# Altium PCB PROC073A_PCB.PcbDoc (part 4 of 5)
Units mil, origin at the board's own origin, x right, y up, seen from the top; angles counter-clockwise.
Board outline 2165.35 x 2165.35 mil, 6 copper layers (Top Layer, L2, L3, L4, L5, Bottom Layer), stack 55.77 mil thick; 284 components, 233 nets, 945 pads, 1419 vias.
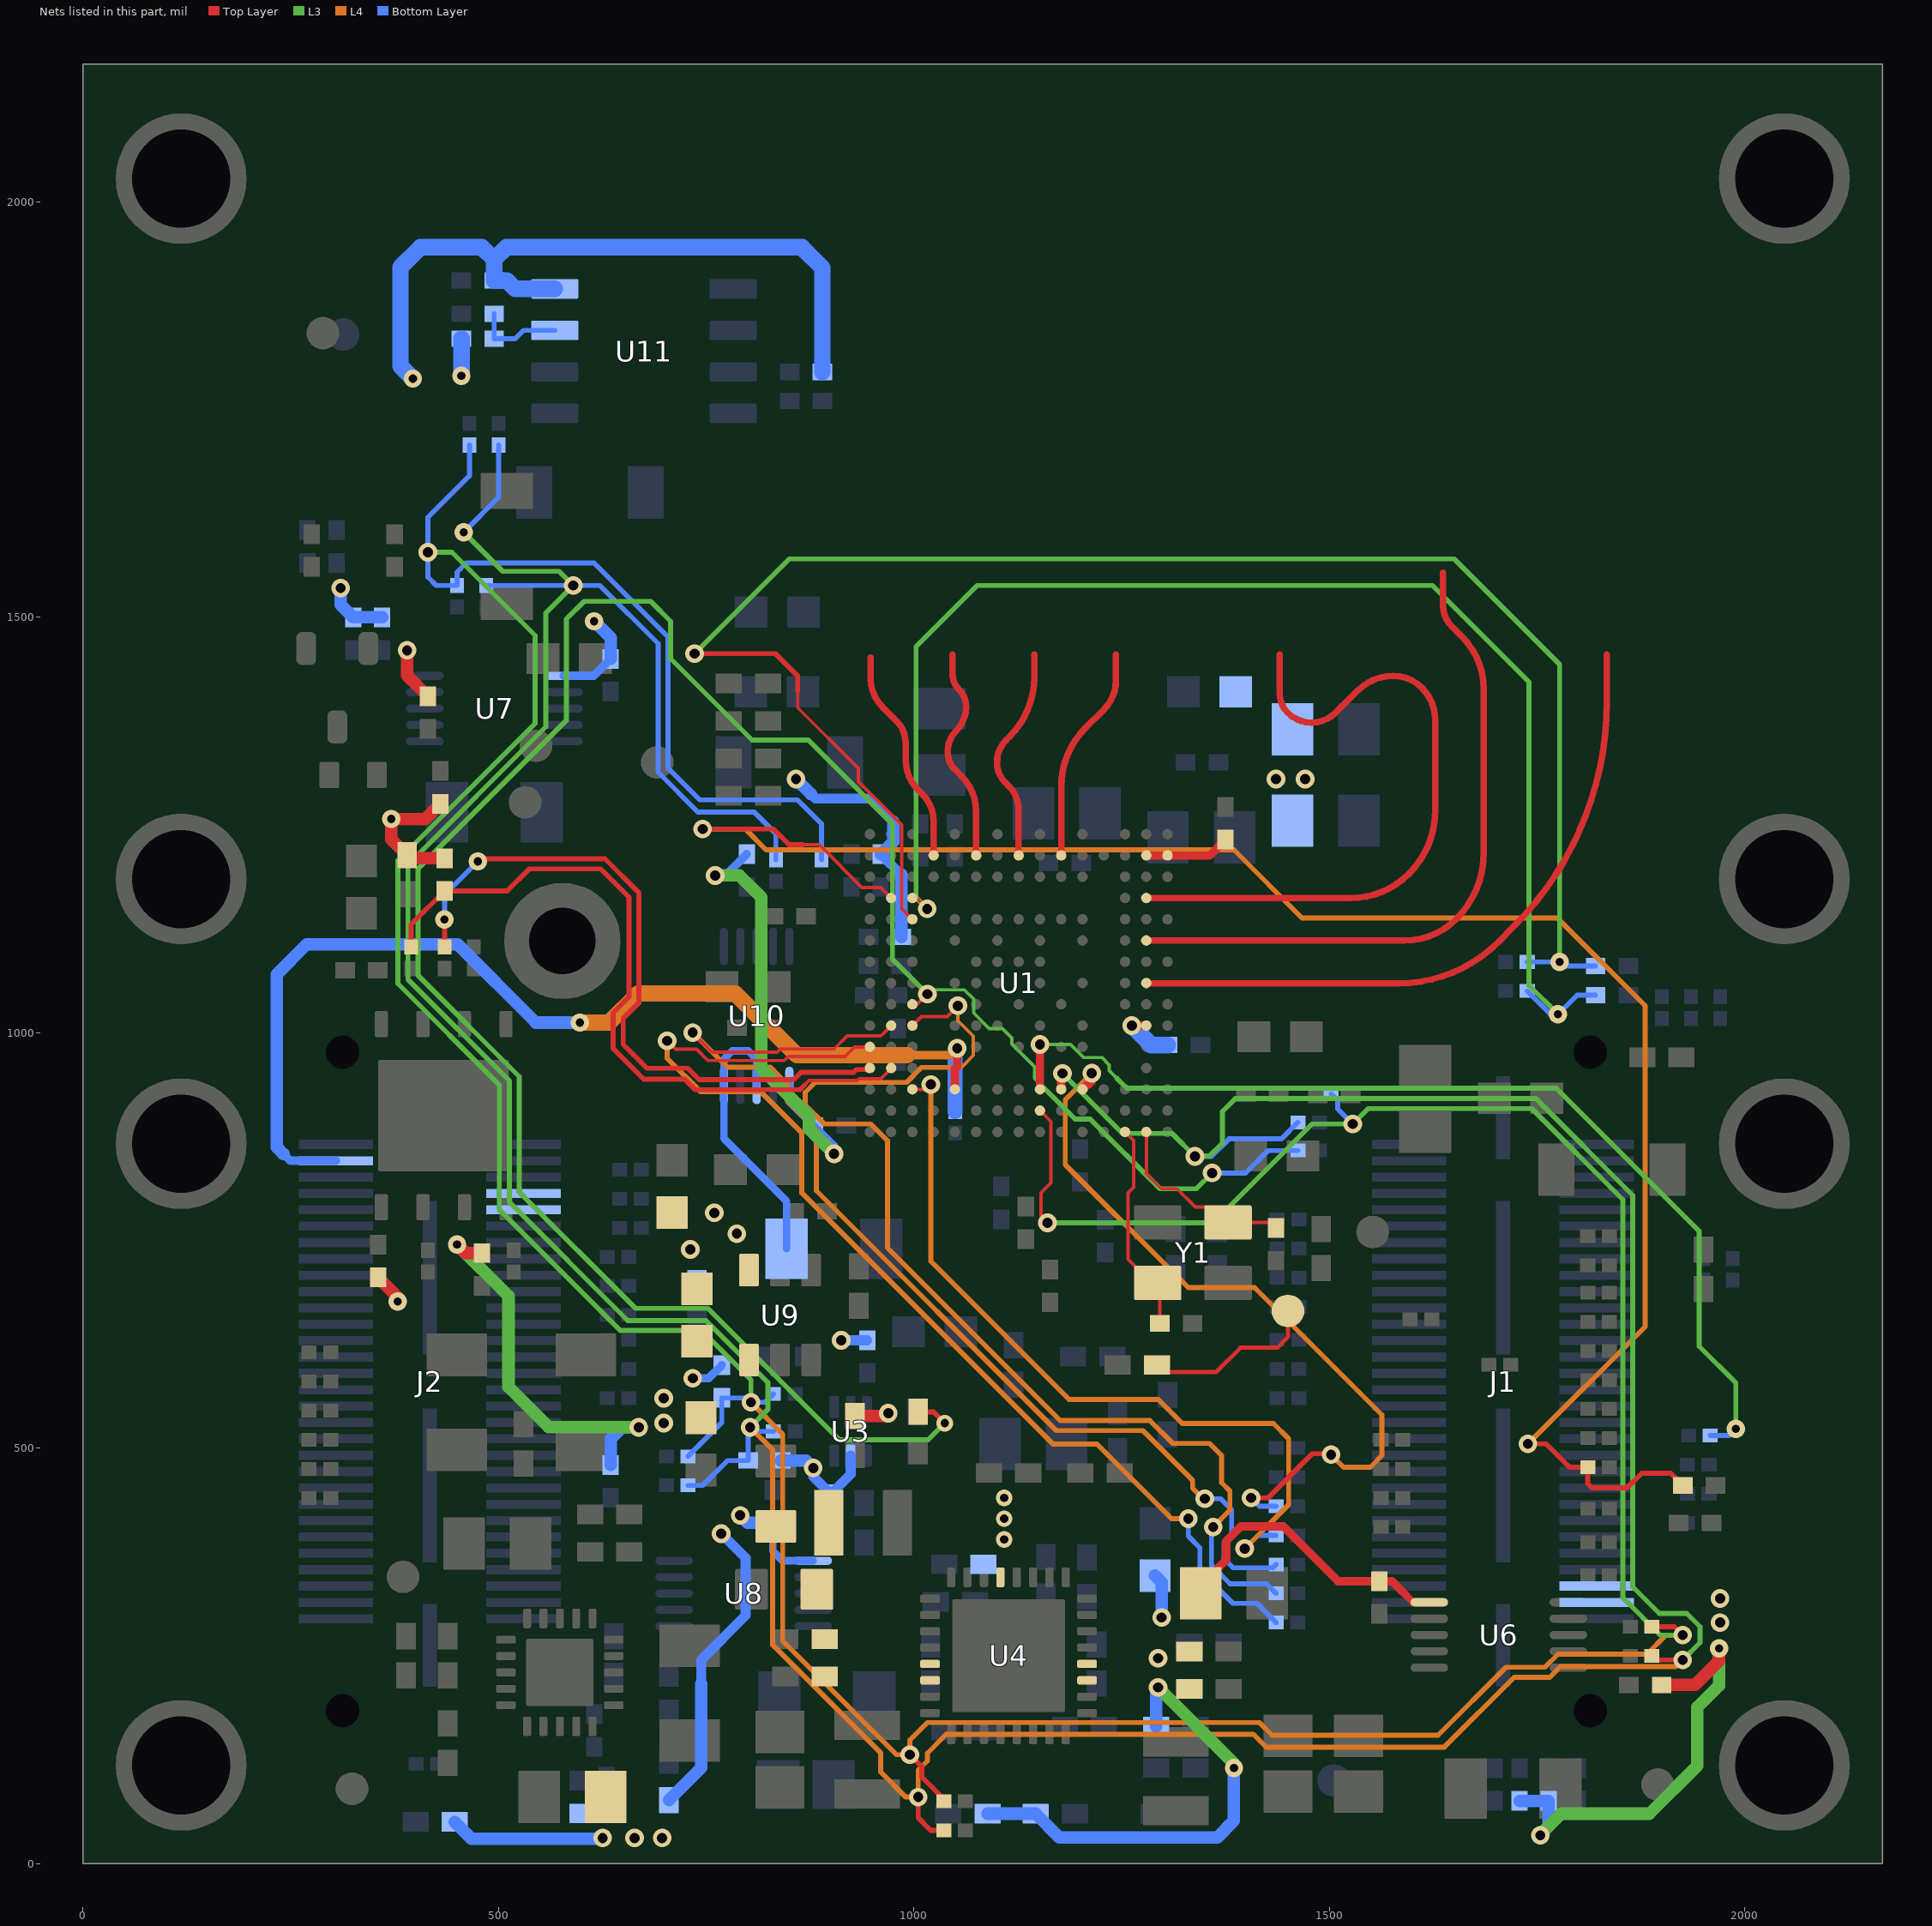
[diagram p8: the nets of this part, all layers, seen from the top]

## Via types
v1: diameter 13.77/15.74 (per signal layer), hole 5.9, Top Layer to L2, tented both sides, 894 vias
v2: diameter 22.4, hole 12.2, Top Layer to Bottom Layer, tented both sides, 340 vias
v3: diameter 13.78/15.75 (per signal layer), hole 5.9, Top Layer to L2, tented both sides, 72 vias
v4: diameter 22, hole 10, Top Layer to Bottom Layer, tented both sides, 54 vias
v5: diameter 20, hole 10, Top Layer to Bottom Layer, tented both sides, 35 vias
v6: diameter 13.77/15.74 (per signal layer), hole 5.9, Top Layer to L2, tented top, 14 vias
v7: diameter 19.68, hole 7.87, Top Layer to Bottom Layer, tented both sides, 9 vias
v8: diameter 13.78/15.75 (per signal layer), hole 5.9, Top Layer to L2, tented top, 1 vias

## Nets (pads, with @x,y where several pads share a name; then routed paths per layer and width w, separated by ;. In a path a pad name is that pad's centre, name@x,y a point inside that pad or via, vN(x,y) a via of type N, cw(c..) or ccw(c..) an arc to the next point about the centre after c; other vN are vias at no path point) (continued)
RADAR_QSPI_D3: R49.1 R51.2 U1.P12 | length 887.1
  Top Layer w4: 868.06,936.7 873.56,942.2 931.63,942.2 933.98,944.55 960.14,944.55 U1.P12@972.64,957.05
  Top Layer w6: R51.2@395,1102.99 395,1130.31 R49.1@435,1170.32 510.31,1170.31 537.01,1197.01 623.01,1197.01 657,1163.03 657,1043 638,1024 638,980.74 674.74,944 723.68,944 736.48,931.2 862.56,931.2 868.06,936.7
RADAR_QSPI_SCLK: R48.2 U1.R12 | length 842.2
  Top Layer w4: U1.R12@945.56,955.56 U1.R12@947.05,957.05
  Top Layer w6: R48.2@435,1102.99 v4(435,1135.99) ; v4(475,1206) 478.01,1209.01 627.98,1209.01 669,1168 669,1036 650,1017 650,985.71 678.71,957 727.65,957 741.31,943.34 855.27,943.34 864.13,952.2 927.49,952.2 930.85,955.56 U1.R12@945.56,955.56
  Bottom Layer w6: v4(435,1135.99) 435,1166 v4(475,1206)
RADAR_RS232RX: R38.1 R154.1 U1.N4 | length 1678.4
  Top Layer w4: U1.N4@998.03,1161.98 1002.76,1161.98 v2(1015.87,1148.87)
  L3 w5.98: v2(1015.87,1148.87) 1002.43,1162.31 1002.43,1464.43 1076,1538 1624,1538 1740,1422 1740,1057 v4(1775,1022)
  Bottom Layer w5.98: R38.1@1737.99,1050 1765.99,1022 v4(1775,1022) 1798,1045 R154.1@1820.32,1045
RADAR_RS232TX: R40.1 R153.1 U1.N5 | length 2068.6
  Top Layer w4: 860,1410.95 860,1391 933,1318 933,1301.91 985.23,1249.68 985.23,1246.17 ; 985.28,1246.17 985.28,1149.13 U1.N5@998.23,1136.18
  Top Layer w6: v2(736,1456) 833.25,1456 860,1429.25 860,1410.95
  L3 w6: v2(736,1456) 850,1570 1650,1570 1777,1443 v4(1777,1085)
  Bottom Layer w6: R40.1@1737.99,1085 v4(1777,1085) 1782,1080 R153.1@1820.32,1080
RADAR_SCL: R25.2 R37.1 R53.1 R56.1 R89.1 R108.2 R109.2 R143.2 R159.2 U1.G14 | length 5694.7
  Top Layer w4: U1.G14@1151.57,906.07 1164.57,893.07 1164.57,819.01 1152.89,807.33 1152.89,778.7 v2(1160.59,771)
  Top Layer w6: v2(995,131) 1009.5,116.5 1009.5,104.07 1035.75,77.81 R89.1@1035.75,75 ; R25.2@1887.99,285 1915,285 v2(1925,275)
  L3 w6: v2(415,1578) 444,1578 544,1478 544,1371.91 379,1206.91 379,1059 501,937 501,787 646.5,641.5 744.5,641.5 803.74,582.26 v2(803.74,555) ; v2(1160.59,771) 1360,771 1479,890 v2(1528,890) 1546.52,908.52 1743.48,908.52 1853,799 1853,320 1898,275 v2(1925,275)
  L4 w6: v2(803.74,555) 842,516.74 842,268 979,131 v2(995,131) 995,148.42 1016.23,169.65 1415.8,169.65 1430.91,154.53 1630.76,154.53 1712.36,236.14 1759.14,236.14 1775,252 1882,252 1905,275 v2(1925,275)
  Bottom Layer w6: R159.2@465,1707.01 465,1670 415,1620 v2(415,1578) 415,1548 425.01,1537.99 R108.2@450,1537.99 450,1553.99 461,1565 615,1565 704,1476 704,1318.2 742.08,1280.12 859.88,1280.12 888.74,1251.26 R143.2@888.74,1207.99 ; R109.2@727.99,490 768.74,530.75 R53.1@768.74,560.32 798.43,560.31 v2(803.74,555) 820.75,555 R56.1@830.75,565 ; R37.1@1502.01,926 1509.94,918.07 1509.94,908.06 v2(1528,890) v2@1526.45,890
RADAR_SDA: R29.2 R34.1 R52.1 R55.1 R88.1 R110.2 R111.2 R144.2 R160.2 U1.F13 | length 5642.3
  Top Layer w6: v2(1005,80) 1005,55 1020,40 R88.1@1035.75,40 ; R29.2@1887.99,250 1892.99,245 v2(1925,245)
  Top Layer w10: U1.F13@1177.16,931.66 1177.15,949.42 v2(1178.55,950.82)
  L3 w6: v4(458,1602) 505,1555 572.99,1555 v2(590,1537.99) 557,1504.99 557,1367.94 391,1201.94 391,1063.97 513,941.97 513,796 655.5,653.5 749.53,653.5 824.01,579.01 824.01,546.27 v2(802.74,525) ; v2(1178.55,950.82) 1250.82,878.55 1310.44,878.55 v2(1338,851) 1338.2,851.2 1355.2,851.2 1371,867 1371,904.83 1386.69,920.52 1748.45,920.52 1865,803.97 1865,333 1897,301 1930,301 1946,285 1946,266 v2(1925,245)
  L4 w6: v2(802.74,525) 830,497.74 830,263.03 960,133.03 960,110 990,80 v2(1005,80) 1005,112.43 1016,123.43 1016,132.87 1038.6,155.47 1408.41,155.47 1423.76,140.11 1638.15,140.11 1722.17,224.14 1765.14,224.14 1778.03,237.03 1917.03,237.03 v2(1925,245)
  Bottom Layer w6: v4(458,1602) 500,1644 R160.2@500,1707.01 ; R110.2@485,1537.99 v2(590,1537.99) 622.01,1537.99 692,1468 692,1313.23 740.03,1265.2 807.8,1265.2 833.74,1239.26 R144.2@833.74,1207.99 ; R111.2@727.99,455 745.55,455 775.55,485 R52.1@800.32,485 800.31,522.57 v2(802.74,525) 807.74,520 R55.1@830.75,520 ; v2(1338,851) 1358,851 1379,872 1442.01,872 R34.1@1462.01,892
RADAR_SPICLK1: R9.1 U1.E13 | length 928.1
  Top Layer w6: v2(1405.74,440) 1426,440 1479.2,493.2 v2@1501,493.2
  Top Layer w10: U1.E13@1202.75,931.66 1208.65,937.57 1210.37,937.57 1213.87,941.08 v2(1213.87,951.07)
  L4 w6: v2(1213.87,951.07) 1182,919.19 1182,841 1330,693 1409.75,693 1563,539.75 1563,491 1549,477 1517,477 v2(1502,492) ; v2@1502.11,493.2 v2@1502.65,492.65
  Bottom Layer w6: v2(1405.74,440) 1415.74,430 R9.1@1435.75,430
RADAR_SYNC_IN: R36.2 R155.2 U1.P4 | length 2302.7
  Top Layer w4: 865.59,1226 885.9,1226 937.33,1174.57 959.84,1174.57 U1.P4@972.43,1161.98
  Top Layer w6: v2(745.59,1245) 830.59,1245 849.59,1226 865.59,1226 ; v2(1738.74,505) 1760.75,505 1788.9,476.85 R36.2@1810.75,476.85 1810.75,457.25 1816,452 1858,452 1875.8,469.8 1910.51,469.8 R155.2@1925.31,455
  L4 w6: v2(745.59,1245) 796.96,1245 821.96,1220 1384.92,1220 1467.17,1137.75 1774.25,1137.75 1879.76,1032.24 1879.76,646.02 v2(1738.74,505)
RADAR_SYNC_OUT_SOP1: R16.2 U1.G13 | length 1235.2
  Top Layer w10: v2(1151.47,985.62) 1151.47,967.42 1151.56,967.33 U1.G13@1151.57,931.66
  L3 w4: v2(1151.47,985.62) 1188.38,985.62 1204,970 1226,970 1235,961 1235,954 1244.04,944.96
  L3 w6: 1244.04,944.96 1256,933 1772.92,933 1945,760.92 1945,622.52 1989,578.52 v4(1989,523)
  Bottom Layer w6: R16.2@1957.99,515 1981,515 v4(1989,523)
RADAR_TCK: R6.2 U1.P10 | length 1340.2
  Top Layer w4: v2(733.59,1000) 757.25,976.34 835.53,976.34 839.39,980.2 903.92,980.2 919.59,995.87 959.83,995.87 962.72,998.76 962.82,998.76 U1.P10@972.43,1008.43 U1.P10@972.43,1008.43
  L4 w5.98: v2(733.59,1000) 775.11,958.48 826.52,958.48 847.57,937.43 847.57,917.44 882.35,882.66 882.35,809.72 1171.05,521.01 1275.43,521.01 1335.19,461.25 1335.19,451.53 1347.73,439 v2(1350,439)
  Bottom Layer w5.98: v2(1350,439) 1369,439 1382.29,425.7 1382.29,396.01 1373.02,386.74 1373.02,366.98 1384,356 1431.75,356 R6.2@1435.75,360
RADAR_TDI: R5.1 U1.R11 | length 1366.2
  Top Layer w4: v2(703,990) 713,980 738.37,980 752.03,966.34 843.97,966.34 848.83,971.2 916.79,971.2 928.23,982.64 U1.R11@947.05,982.64
  L4 w6: v2(703,990) 703,969 743.4,928.59 815.62,928.59 865.09,879.12 865.09,806.91 1167.08,504.92 1220,504.92 1309.91,415 v2(1330,415)
  Bottom Layer w6: v2(1330,415) 1330,394 1344,380 1344,352.67 1383.67,313 1412.75,313 R5.1@1435.75,290
RADAR_TDO_SOP0: R4.2 U1.N13 | length 955
  Top Layer w4: U1.N13@998.03,931.66 1014.37,931.67 v2(1020.27,937.57)
  L4 w5.98: v2(1020.27,937.57) 1020.27,724.72 1186.6,558.4 1293.91,558.4 1322.79,529.52 1432.48,529.52 1450.82,511.18 1450.82,431.82 v2(1398,379)
  Bottom Layer w5.98: v2(1398,379) 1414,395 R4.2@1435.75,395
RADAR_TMS: R8.2 U1.N10 | length 1356.4
  Top Layer w4: U1.N10@998.03,1008.43 1008.97,1019.39 1039.8,1019.39 v2(1052.67,1032.26)
  L4 w4.02: 1048,958 1056.74,958 1071.23,972.49 1071.23,995.77 1052.67,1014.32 v2(1052.67,1032.26)
  L4 w6: 1048,958 1009,958 991,940 881,940 869,928 869,912.97 891.97,890 948,890 968,870 968,741.03 1176.02,533.01 1283.99,533.01 1311.47,505.53 1355.69,505.53 1370.2,491.01 1370.2,458.37 1380.2,448.37 1380.2,425.2 v2(1360,405)
  Bottom Layer w6: v2(1360,405) 1358.01,403.01 1358.01,358.99 1380.5,336.5 1424.25,336.5 R8.2@1435.75,325
RADAR_VBGAP: C6.2 U1.B10 | length 70.4
  Top Layer w10: v2(1262.07,1008.44) U1.B10@1279.52,1008.43
  Bottom Layer w20: v2(1262.07,1008.44) 1285.51,985 C6.2@1305.31,985
RADAR_VOUT_PA: C4.2 C7.2 C8.2 R1.2 U1.A2 U1.B2 | length 102.2
  Top Layer w10: U1.B2@1279.72,1212.95 1355.41,1212.95 C4.2@1374.18,1231.72
  other v2: 1435.59,1305 1470.59,1305
RADAR_VSENSE: R77.1 TP7.1 | length 210.1
  Top Layer w5: R77.1@1292.36,600 1300.89,591.48 1363.55,591.48 1392.82,620.75 1437.23,620.75 1450,633.52 TP7.1@1450,665
RADAR_WARMRST: R64.2 R98.1 U1.N9 | length 2868.1
  Top Layer w4: U1.N9@998.03,1034.03 1003.79,1034.03 v2(1016.02,1046.26)
  Top Layer w6: R98.1@1005,543.62 1023.38,543.62 v5(1037,530)
  L3 w4: v2(1016.02,1046.26) 1021.22,1051.46 1060.63,1051.46 1071.87,1040.21 1071.87,1023.56 1090.58,1004.86 1106.38,1004.86 1117.62,993.61 1117.62,986.26 1145.07,958.81 1145.07,944.66 1155.24,934.5
  L3 w6: v2(1016.02,1046.26) 974,1088.28 974,1251 873,1352 805,1352 707,1450 707,1495 683,1519 603,1519 581.5,1497.5 581.5,1375.47 403,1196.97 403,1068.94 525,946.94 525,808 665,668 752,668 910.05,509.95 1016.95,509.95 v5(1037,530) ; 1155.24,934.5 1193.74,896 1212,896 1296,812 1339.74,812 v2(1358.74,831)
  Bottom Layer w6: v2(1358.74,831) 1399,831 1426,858 R64.2@1462.01,858
RADAR_XTALM: C33.2 U1.C15 Y1.1 | length 257.6
  Top Layer w4: U1.C15@1253.93,880.48 1264.41,870 1264.41,813.82 1257.72,807.13 1257.72,727 1286.14,698.58 Y1.1@1293.27,698.58 1295.9,695.94 C33.2@1295.91,650
RADAR_XTALP: C32.2 U1.B15 Y1.3 | length 233.3
  Top Layer w4: U1.B15@1279.72,880.27 1279.72,829.86 1297.59,812 1316.59,812 1338.59,790 1359.33,790 Y1.3@1377.91,771.42 1428.86,771.42 C32.2@1435.59,764.69
RX1: U1.M2 | length 261.6
  Top Layer w7.8: 947.77,1451.18 947.77,1426.14 ccw(c995.92,1426.14) 961.87,1392.09 978.76,1375.2 cw(c951.21,1347.65) 990.17,1347.65 990.17,1327.22 ccw(c1039.3,1327.22) 1004.54,1292.5 1009.93,1287.11 cw(c976.89,1254.07) 1023.62,1254.07 U1.M2@1023.62,1213.16
RX2: U1.K2 | length 262.5
  Top Layer w7.8: 1046.2,1454.95 1046.2,1432.54 ccw(c1075.16,1432.54) 1054.68,1412.06 cw(c1035.22,1392.6) 1062.74,1392.6 cw(c1020.25,1392.6) 1050.29,1362.55 ccw(c1073.36,1339.49) 1040.74,1339.49 1040.74,1336.31 ccw(c1068.05,1336.31) 1048.73,1317.01 1057.06,1308.68 ; 1057.07,1308.67 cw(c1014.23,1265.86) 1074.8,1265.86 U1.K2@1074.8,1213.16
RX3: U1.H2 | length 262.2
  Top Layer w7.8: U1.H2@1125.98,1213.16 1125.98,1272.15 1125.74,1272.39 ccw(c1085.51,1268) 1114.13,1296.61 1109.64,1301.1 cw(c1133.54,1325) 1099.74,1325 cw(c1138.37,1325) 1111.05,1352.31 1115.34,1356.6 ccw(c1044.63,1427.31) 1144.63,1427.31 1144.63,1454.95
RX4: U1.F2 | length 262.7
  Top Layer w7.8: U1.F2@1177.16,1213.16 1177.16,1296 cw(c1277.16,1296) 1206.45,1366.71 1228.74,1389 ccw(c1194.2,1423.54) 1243.05,1423.54 1243.05,1454.95
TX1: U1.B4 | length 820.5
  Top Layer w7.8: U1.B4@1279.72,1161.77 1524.9,1161.77 ccw(c1524.9,1261.77) 1595.61,1191.06 ccw(c1518.88,1267.79) 1627.4,1267.79 1627.39,1375.59 ccw(c1571.48,1375.59) 1611.02,1415.13 ccw(c1576.8,1380.91) 1576.8,1429.3 ccw(c1576.8,1368.95) 1534.13,1411.62 1507.64,1385.13 cw(c1478.35,1414.42) 1478.35,1373 cw(c1478.35,1413.32) 1449.84,1384.81 cw(c1473.81,1408.78) 1439.91,1408.78 1439.91,1454.97
TX2: U1.B6 | length 820.5
  Top Layer w7.8: U1.B6@1279.72,1110.59 1589.93,1110.59 ccw(c1589.93,1198.97) 1652.42,1136.47 ; 1636.76,1553.4 1636.76,1513.49 ccw(c1671.2,1513.49) 1646.84,1489.14 1659.37,1476.61 cw(c1595.52,1412.76) 1685.82,1412.76 1685.82,1217.1 cw(c1571.8,1217.1) 1652.42,1136.47 ; 1652.47,1136.51 cw(c1575.03,1213.87) 1652.42,1136.47
TX3: U1.B8 | length 820.6
  Top Layer w7.08: U1.B8@1279.52,1059.62 U1.B8@1279.72,1059.41
  Top Layer w7.8: U1.B8@1279.72,1059.41 1566.14,1059.41 1583.77,1059.41 ccw(c1583.77,1227.92) 1702.92,1108.77 1721.82,1127.66 ccw(c1451.93,1397.54) 1833.61,1397.54 1833.61,1454.97
VCC_3V3: C36.2 C37.2 C38.2 C42.1 C43.2 C45.2 C49.1 C50.1 C54.1 C56.1 C57.2 C58.2 C59.2 C62.2 C63.2 C65.2 J1.4 J1.6 J2.7 J2.9 L6.1 R2.2 R14.2 R43.2 R44.2 R49.2 R50.1 R52.2 R53.2 R54.2 R78.2 R83.2 R87.2 R94.1 R95.2 R104.2 R105.2 R106.2 R107.2 R112.1 R115.1 R118.2 R122.1 R138.1 R139.2 R141.2 R142.2 R145.1 R148.2 R157.2 R161.2 U3.5 U4.5 U4.13 U4.14 U4.27 U4.28 U6.6 U7.6 U8.6 U9.1 U10.6 U11.8 | length 5197.8
  Top Layer w9: 1589,326 1600.63,314.37 U6.6@1620.08,314.37
  Top Layer w10: C37.2@1361,350.5 1375.8,365.3 1375.8,388.19 1393.3,405.7 1444.3,405.7 1510.31,339.68 1575.31,339.68 1589,326
  Top Layer w15: R50.1@355,705.32 378.74,681.57 v4(378.74,676.26) ; v2(390,1460) 390,1429.68 R112.1@415,1404.68 ; R78.2@430,1275.31 411.68,1257 v4(371,1257) 371,1232.62 393.94,1209.68 R49.2@435,1209.69 ; v4(450,745) 460.31,734.68 R44.2@480,734.69 ; R87.2@929,538.62 965.62,538.62 v2(969,542) ; R94.1@1899.68,215 1940,215 1969,244 v4(1969,259)
  L3 w15: v4(450,745) 512,683 512,573.5 560.5,525 v2(668.74,525) ; v2(760.74,1189) 790,1189 816,1163 816,957.14 873.44,899.7 873.44,884.3 v2(903.74,854) ; v2(1293.74,212) 1385,120.74 v4(1385,115) ; v2(1753.74,34) 1753.74,34.93 1778.81,60 1885,60 1942.7,117.7 1942.7,188 1969,214.3 v4(1969,259)
  Bottom Layer w9: C59.2@830,410.31 830,375.93 841.56,364.37 U8.6@878.66,364.37
  Bottom Layer w10: U7.6@578.66,1429.37 614.68,1429.37 C58.2@635,1449.69 ; v2(733.74,584) 753.05,584 R53.2@768.74,599.69 ; v2(760.74,1189) 773.06,1189 R145.1@798.74,1214.69 ; U10.6@849.96,936.34 849.96,917.28 903.74,863.5 v2(903.74,854)
  Bottom Layer w12: 743.86,216.15 743.86,245.05 797.39,298.58 797.39,367.61 v2(768,397) ; 876,1287 881.49,1281.5 947.02,1281.5 975,1253.52 ; v2(878.74,476) 878.74,465.94 C36.2@900,444.69 923.74,468.43 U3.5@923.74,490.87 ; v2(912.43,629.68) R54.2@943.74,629.69 ; R139.2@960,1214.69 984.68,1190
  Bottom Layer w15: v2(310,1535) 310,1514.68 R105.2@325,1499.69 R104.2@360,1499.69 ; R148.2@447.36,50 467.36,30 624.49,30 v2(625.2,30.71) ; v4(615,1495) 635,1475 C58.2@635,1449.69 ; R115.1@635,479.68 635,511 649,525 v2(668.74,525) ; R83.2@705,76.38 743.86,115.24 743.86,216.15 ; v2(790.74,419) 799.43,410.31 C59.2@830,410.31 ; R52.2@839.69,485 869.74,485 v2(878.74,476) ; v2(858,1305) 876,1287 ; R139.2@960,1214.69 975,1229.68 975,1253.52 ; R142.2@984.69,1115 984.68,1190 ; R118.2@1088.62,60 R141.2@1146.38,60 1174.85,31.53 1365,31.53 1385,51.53 v4(1385,115) ; R122.1@1290,346.5 1298,338.5 v2(1298,296) ; R95.2@1291.38,165 1291.38,209.63 v2(1293.74,212) ; R2.2@1728.74,75.32 R14.2@1763.74,75.32 1763.74,44.93 1753.74,34.93 v2(1753.74,34)
  Bottom Layer w20: v4(397,1787) 382,1802 382,1921 406,1945 480,1945 494.68,1930.31 ; v4(455.31,1790.31) R157.2@455.31,1835 ; U11.8@567.72,1895 520,1895 510,1905 C65.2@494.69,1905 494.68,1930.31 ; R161.2@889.69,1795 889.68,1920.31 865,1945 509.37,1945 494.68,1930.31
  other v2: 663.74,30.71 696.85,30.71 1293.74,247 1970,290 1970,319 698.74,530 698.74,560
  other v5: 1108.43,390 1108.43,415 1108.43,440
VCC_LD_SW_3V3: C51.1 R119.1 R123.1 R138.2 U9.6 U10.8 U10.10 | length 338.6
  Bottom Layer w9: U10.8@810.59,936.34 810.59,968 800.59,978 781.22,978 771.22,968 771.22,872.52 846.65,797.08 R123.1@846.65,740
  other v2: 730.74,739 786.74,758 759.74,783
VPP_1P7: C31.2 J2.4 U1.L13 | length 1333.3
  Top Layer w10: U1.L13@1049.21,931.66 1049.2,956.34 1052.02,959.16 v2(1052.02,981.06)
  L4 w10: 991.82,972.82 1043.78,972.82 v2(1052.02,981.06)
  L4 w19.68: v4@600,1012 633.04,1012 668.04,1047 785,1047 859.18,972.82 991.82,972.82
  Bottom Layer w10: 241.12,853.87 249.25,845.75 J2.4@304.44,845.75
  Bottom Layer w15: 241.12,853.87 233,862 233,1070 269,1106 451,1106 545,1012 v4(598,1012)
  Bottom Layer w18: C31.2@1049.59,904.99 1049.59,978.62 v2(1052.02,981.06)
WP#: R157.1 R158.2 U11.7 | length 107.2
  Bottom Layer w6: R158.2@494.69,1865 R157.1@494.68,1835 520,1835 530,1845 U11.7@567.72,1845
pads on no net: FID1.1 FID2.1 FID3.1 FID4.1 FID5.1 FID6.1 J1.MH1 J1.MH2 J2.6 J2.8 J2.10 J2.12 J2.14 J2.16 J2.26 J2.28 J2.35 J2.37 J2.39 J2.41 J2.43 J2.44 J2.45 J2.46 J2.47 J2.48 J2.49 J2.50 J2.51 J2.52 J2.53 J2.54 J2.55 J2.56 J2.57 J2.58 J2.59 J2.60 J2.MH1 J2.MH2 LBL1.0 U2. U4. U5.5 U11.1 U11.2

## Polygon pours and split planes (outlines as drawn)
RADAR_1V2 on Top Layer "TOP-No Net 1" (solid, remove dead copper, pour order 166): 835.59,885 860.59,885 910.59,835 955.59,835 970.59,820 970.59,810 930.59,770 885.59,770 885.59,804.99 875.59,815 825.59,815 820.59,820 820.59,870
PMIC_1V0 on Top Layer "TOP-No Net 1" (solid, remove dead copper, pour order 202): 660.89,909.56 676.74,897.82 676.74,712 692,696.74 692,596 678,582 416.74,582 412.74,586 412.74,642.74 425,655 537.74,655 578.99,696.25 579,880.38 608.18,909.56
PMIC_1V24 on Top Layer "PMIC_1V24_L01_P466" (solid, remove dead copper, pour order 466): 19 vertices, not listed, extent 640.76,20.49 986.35,173.02
RADAR_3V3 on Top Layer "RADAR_3V3_L01_P220" (solid, remove dead copper, pour order 220): 815,1075 815,995 820,990 900,990 905,995 905,1010 890,1025 885,1025 865,1045 865,1065 855,1075
5V_IN on Top Layer "5V_IN_L01_P224" (solid, remove dead copper, pour order 224): 20 vertices, not listed, extent 249,234 360,920
RADAR_1V8 on Top Layer "RADAR_1V8_L01_P222" (solid, remove dead copper, pour order 222): 22 vertices, not listed, extent 1580.78,790.08 1718.65,942.5
PMIC_1V8 on Top Layer "PMIC_1V8_L01_P216" (solid, remove dead copper, pour order 216): 1385,81 1417,113 1588,113 1615,140 1687,140 1689,138 1689,45 1664,20 1274,20 1266,28 1266,74 1273,81
VCC_3V3 on Top Layer "VCC_3V3_L01_P214" (solid, remove dead copper, pour order 214): 1198.74,245 1261.74,245 1280,263.26 1280,350 1292,361.99 1370,362 1370,293 1347,270 1347,196 1341,190 1258,190 1233,215 1198.74,215
NetL4_1 on Top Layer "TOP-No Net 1" (solid, remove dead copper, pour order 212): 1196.74,205 1225.74,205 1253.74,177 1349,177 1359.99,166 1360,133 1354.99,127.99 1242.74,128 1196.74,174
RADAR_3V3 on Top Layer "RADAR_3V3_L01_P210" (solid, remove dead copper, pour order 210): 1101,727 1151,727 1157,733 1169,733 1174,728 1174,706 1170.99,702.99 1148,703 1145,700 1100,700 1094,706 1094,720
RADAR_1V2 on Top Layer "RADAR_1V2_L01_P208" (solid, remove dead copper, pour order 208): 600,1475 695,1475 705,1465 705,1430 680,1405 610,1405 595,1420 595,1470
CB_PMIC_1V2 on Top Layer "CB_PMIC_1V2_L01_P206" (solid, remove dead copper, pour order 206): 464,1540 549.98,1540 574.01,1516.01 574.01,1479.01 574,1410 564,1400 493,1400 446,1447 446,1522
GND on Top Layer "TOP-No Net" (solid, remove dead copper, pour order 200): 1028.74,294.32 994.74,294.32 958.67,294.31 947,306.01 947,316 957,326 981.06,326 1002.74,304.31 1028.74,304.32
CB_PMIC_1V8 on Top Layer "CB_PMIC_1V8_L01_P196" (solid, remove dead copper, pour order 196): 1755,165 1780,165 1795,150 1840,150 1845,145 1845,75 1825,55 1750,55 1750,160
GND on Top Layer "TOP-No Net 1" (solid, remove dead copper, pour order 192): 784.74,504 773.74,493 717.74,493 708.74,484 708.74,404.99 715.74,398 735,398 765.74,428.74 765.74,443 779.74,457 851.74,457 858.74,464 858.74,501.99 856.74,504
VCC_3V3 on Top Layer "TOP-No Net 1" (solid, remove dead copper, pour order 188): 603.74,115 652.52,115 712.74,54.78 712.74,24 705.74,17 611.74,17 603.74,25
GND on Top Layer "TOP-No Net 1" (solid, remove dead copper, pour order 186): 18 vertices, not listed, extent 470,35 648.23,272.02
GND on Top Layer "TOP-No Net 1" (solid, remove dead copper, pour order 184): 17 vertices, not listed, extent 511.74,221 628.74,443
GND on Top Layer "TOP-No Net 1" (solid, remove dead copper, pour order 180): 1040.74,168.99 1068.74,169 1070.75,166.99 1070.74,120 1060.74,110 1060.74,101 1053.74,94 1037,94 1022,109 1022,135.26 1036.74,150 1036.74,165
GND on Top Layer "TOP-No Net 1" (solid, remove dead copper, pour order 178): 1157.06,168 1188.06,168 1188.06,151 1214.06,125 1214.06,90 1174,90 1157.06,106.94
VCC_3V3 on Top Layer "TOP-No Net 1" (solid, remove dead copper, pour order 176): 1098.43,450 1118.43,450 1118.43,385 1109.43,376 1109.43,332 1098.43,332
GND on Top Layer "TOP-No Net 1" (solid, remove dead copper, pour order 174): 1128.43,435 1148.43,435 1148.43,387.68 1129.43,368.69 1129.43,332 1118.43,332 1118.43,373.69 1128.43,383.68
VCC_3V3 on Top Layer "TOP-No Net 1" (solid, remove dead copper, pour order 172): 19 vertices, not listed, extent 754,215 1033.74,454
NetL6_2 on Top Layer "TOP-No Net 1" (solid, remove dead copper, pour order 170): 958.74,364.99 1009.73,314 1031.74,314 1031.74,357 1003.74,385 1003.74,457 958.74,457
NetL5_1 on Top Layer "TOP-No Net 1" (solid, remove dead copper, pour order 168): 919.74,205 1030.74,205 1030.74,173 1021.74,164 999.74,164 982.74,147 904.74,147 902.74,149 902.74,188
VCC_3V3 on Top Layer "TOP-No Net 1" (solid, remove dead copper, pour order 164): 713.74,650 788.74,650 813.74,625 813.74,594 778.74,559 778.74,525 766.74,513 664.74,513 655.74,521.99 655.74,544.73 713.74,602.74
VCC_LD_SW_3V3 on Top Layer "TOP-No Net 1" (solid, remove dead copper, pour order 162): 691.74,806 767.73,806 813.74,760 813.74,695 788.74,670 718.74,670 708.74,680 708.74,716 686.74,738 686.74,801
NetC61_1 on Top Layer "TOP-No Net" (solid, remove dead copper, pour order 160): 1049.74,335 1049.74,369 1040.74,378 1040.74,421 1032.73,429 1019.74,429 1011.74,421 1011.74,389 1039.74,361 1039.74,335
GND on Top Layer "TOP-No Net" (solid, remove dead copper, pour order 156): 1976.7,2106 1976.77,2143.92 809.74,2144.06 809.74,2106
GND on Top Layer "TOP-No Net 17" (solid, remove dead copper, pour order 150): 94 vertices, not listed, extent 1193.85,1449.32 1292.27,1922.31
GND on Top Layer "OUTLINE-No Net" (solid, remove dead copper, pour order 148): 1787.47,1516.35 1787.47,1461.06 1805.98,1461.06 1805.98,1449.34 1821.73,1449.34 1821.73,1476.81 1803.22,1476.81 1803.22,1500.61 1821.73,1500.61 1821.73,1541.46 1805.98,1541.46 1805.98,1516.35 1787.47,1516.35
TX3 on Top Layer "TOP-RX1 72" (solid, pour order 146): 1835.62,1719.69 1831.62,1719.69 1831.62,1659.14 1835.62,1659.14 1835.62,1719.69
GND on Top Layer "OUTLINE-No Net" (solid, remove dead copper, pour order 144): 1894.77,1922.33 1772.47,1922.33 1772.47,1906.58 1894.77,1906.58 1894.77,1922.33
TX3 on Top Layer "TOP-RX1 73" (solid, pour order 142): 1835.62,1828.28 1831.62,1828.28 1831.62,1767.72 1835.62,1767.72 1835.62,1828.28
GND on Top Layer "TOP-GND 25" (solid, remove dead copper, pour order 140): 1894.77,1580.83 1845.52,1580.83 1845.52,1565.09 1894.77,1565.09
TX3 on Top Layer "TOP-RX1 74" (solid, pour order 138): 1837.52,1541.46 1829.73,1541.46 1829.73,1503.28 1837.52,1503.28 1837.52,1541.46
GND on Top Layer "OUTLINE-No Net" (solid, remove dead copper, pour order 136): 1821.73,1580.83 1772.47,1580.83 1772.47,1565.09 1821.73,1565.09 1821.73,1580.83
TX3 on Top Layer "TOP-RX1 75" (solid, pour order 134): 1837.52,1503.28 1829.73,1503.28 1829.73,1488.71 1837.52,1488.71 1837.52,1503.28
GND on Top Layer "OUTLINE-No Net" (solid, remove dead copper, pour order 132): 1821.73,1565.09 1805.98,1565.09 1805.98,1541.46 1821.73,1541.46 1821.73,1565.09
TX3 on Top Layer "TOP-RX1 76" (solid, pour order 130): 1850.51,1507.17 1837.52,1507.17 1837.52,1499.38 1850.51,1499.38 1850.51,1507.17
GND on Top Layer "TOP-GND 26" (solid, remove dead copper, pour order 128): 1861.27,1565.09 1845.52,1565.09 1845.52,1541.46 1861.27,1541.46 1861.27,1565.09
TX3 on Top Layer "TOP-RX1 77" (solid, pour order 126): 1859.21,1659.14 1808.03,1659.14 1808.03,1611.11 1859.21,1611.11 1859.21,1659.14
GND on Top Layer "TOP-GND 27" (solid, remove dead copper, pour order 124): 1861.27,1541.46 1845.52,1541.46 1845.52,1515.17 1858.51,1515.17 1858.51,1491.38 1845.52,1491.38 1845.52,1449.34 1861.27,1449.34 1861.27,1475.63 1874.26,1475.63 1874.26,1530.92 1861.27,1530.92 1861.27,1541.46
TX3 on Top Layer "TOP-RX1 78" (solid, pour order 122): 1837.52,1580.83 1829.73,1580.83 1829.73,1541.46 1837.52,1541.46 1837.52,1580.83
TX3 on Top Layer "TOP-RX1 79" (solid, pour order 120): 1835.62,1611.11 1831.62,1611.11 1831.62,1580.83 1835.62,1580.83 1835.62,1611.11
TX3 on Top Layer "TOP-RX1 80" (solid, pour order 118): 1829.73,1492.61 1811.22,1492.61 1811.22,1484.81 1829.73,1484.81 1829.73,1492.61
TX3 on Top Layer "TOP-RX1 81" (solid, pour order 116): 1871.02,1767.72 1796.22,1767.72 1796.22,1719.69 1871.02,1719.69 1871.02,1767.72
GND on Top Layer "OUTLINE-No Net" (solid, remove dead copper, pour order 114): 1788.22,1906.58 1772.47,1906.58 1772.47,1580.83 1788.22,1580.83 1788.22,1906.58
TX3 on Top Layer "TOP-RX1 83" (solid, pour order 110): 1859.21,1876.31 1808.03,1876.31 1808.03,1828.28 1859.21,1828.28 1859.21,1876.31
GND on Top Layer "OUTLINE-No Net" (solid, remove dead copper, pour order 108): 1894.77,1906.58 1879.02,1906.58 1879.02,1580.83 1894.77,1580.83 1894.77,1906.58
GND on Top Layer "OUTLINE-No Net" (solid, remove dead copper, pour order 106): 1697.92,2005.01 1682.17,2005.01 1682.17,1679.26 1697.92,1679.26 1697.92,2005.01
TX2 on Top Layer "TOP-RX1 83" (solid, pour order 104): 1662.36,1974.73 1611.18,1974.73 1611.18,1926.7 1662.36,1926.7 1662.36,1974.73
GND on Top Layer "OUTLINE-No Net" (solid, remove dead copper, pour order 100): 1591.37,2005.01 1575.62,2005.01 1575.62,1679.26 1591.37,1679.26 1591.37,2005.01
TX2 on Top Layer "TOP-RX1 81" (solid, pour order 98): 1674.17,1866.15 1599.37,1866.15 1599.37,1818.12 1674.17,1818.12 1674.17,1866.15
TX2 on Top Layer "TOP-RX1 80" (solid, pour order 96): 1632.88,1591.03 1614.37,1591.03 1614.37,1583.24 1632.88,1583.24 1632.88,1591.03
TX2 on Top Layer "TOP-RX1 79" (solid, pour order 94): 1638.77,1709.53 1634.77,1709.53 1634.77,1679.26 1638.77,1679.26 1638.77,1709.53
TX2 on Top Layer "TOP-RX1 78" (solid, pour order 92): 1640.67,1679.26 1632.88,1679.26 1632.88,1639.89 1640.67,1639.89 1640.67,1679.26
TX2 on Top Layer "TOP-RX1 77" (solid, pour order 88): 1662.36,1757.57 1611.18,1757.57 1611.18,1709.53 1662.36,1709.53 1662.36,1757.57
GND on Top Layer "TOP-GND 26" (solid, remove dead copper, pour order 86): 1664.42,1663.51 1648.67,1663.51 1648.67,1639.89 1664.42,1639.89 1664.42,1663.51
TX2 on Top Layer "TOP-RX1 76" (solid, pour order 84): 1653.66,1605.6 1640.67,1605.6 1640.67,1597.8 1653.66,1597.8 1653.66,1605.6
GND on Top Layer "OUTLINE-No Net" (solid, remove dead copper, pour order 82): 1624.88,1663.51 1609.13,1663.51 1609.13,1639.89 1624.88,1639.89 1624.88,1663.51
TX2 on Top Layer "TOP-RX1 75" (solid, pour order 80): 1640.67,1601.7 1632.88,1601.7 1632.88,1587.13 1640.67,1587.13 1640.67,1601.7
GND on Top Layer "OUTLINE-No Net" (solid, remove dead copper, pour order 78): 1624.88,1679.26 1575.62,1679.26 1575.62,1663.51 1624.88,1663.51 1624.88,1679.26
TX2 on Top Layer "TOP-RX1 74" (solid, pour order 76): 1640.67,1639.89 1632.88,1639.89 1632.88,1601.7 1640.67,1601.7 1640.67,1639.89
GND on Top Layer "TOP-GND 25" (solid, remove dead copper, pour order 74): 1697.92,1679.26 1648.67,1679.26 1648.67,1663.51 1697.92,1663.51 1697.92,1679.26
TX2 on Top Layer "TOP-RX1 73" (solid, pour order 72): 1638.77,1926.7 1634.77,1926.7 1634.77,1866.15 1638.77,1866.15 1638.77,1926.7
GND on Top Layer "OUTLINE-No Net" (solid, remove dead copper, pour order 70): 1697.92,2020.76 1575.62,2020.76 1575.62,2005.01 1697.92,2005.01 1697.92,2020.76
TX2 on Top Layer "TOP-RX1 72" (solid, pour order 68): 1638.77,1818.12 1634.77,1818.12 1634.77,1757.57 1638.77,1757.57 1638.77,1818.12
GND on Top Layer "OUTLINE-No Net" (solid, remove dead copper, pour order 64): 1393.77,1516.35 1393.77,1461.06 1412.28,1461.06 1412.28,1449.34 1428.02,1449.34 1428.02,1476.81 1409.52,1476.81 1409.52,1500.61 1428.02,1500.61 1428.02,1541.46 1412.28,1541.46 1412.28,1516.35 1393.77,1516.35
TX1 on Top Layer "TOP-RX1 72" (solid, pour order 62): 1441.92,1719.69 1437.92,1719.69 1437.92,1659.14 1441.92,1659.14 1441.92,1719.69
GND on Top Layer "OUTLINE-No Net" (solid, remove dead copper, pour order 60): 1501.07,1922.33 1378.77,1922.33 1378.77,1906.58 1501.07,1906.58 1501.07,1922.33
TX1 on Top Layer "TOP-RX1 73" (solid, pour order 58): 1441.92,1828.28 1437.92,1828.28 1437.92,1767.72 1441.92,1767.72 1441.92,1828.28
GND on Top Layer "TOP-GND 25" (solid, remove dead copper, pour order 56): 1501.07,1580.83 1451.82,1580.83 1451.82,1565.09 1501.07,1565.09 1501.07,1580.83
TX1 on Top Layer "TOP-RX1 74" (solid, pour order 54): 1443.82,1541.46 1436.02,1541.46 1436.02,1503.28 1443.82,1503.28 1443.82,1541.46
GND on Top Layer "OUTLINE-No Net" (solid, remove dead copper, pour order 52): 1428.02,1580.83 1378.77,1580.83 1378.77,1565.09 1428.02,1565.09 1428.02,1580.83
TX1 on Top Layer "TOP-RX1 75" (solid, pour order 50): 1443.82,1503.28 1436.02,1503.28 1436.02,1488.71 1443.82,1488.71 1443.82,1503.28
GND on Top Layer "OUTLINE-No Net" (solid, remove dead copper, pour order 48): 1428.02,1565.09 1412.28,1565.09 1412.28,1541.46 1428.02,1541.46 1428.02,1565.09
TX1 on Top Layer "TOP-RX1 76" (solid, pour order 46): 1456.81,1507.17 1443.82,1507.17 1443.82,1499.38 1456.81,1499.38 1456.81,1507.17
GND on Top Layer "TOP-GND 26" (solid, remove dead copper, pour order 44): 1467.57,1565.09 1451.82,1565.09 1451.82,1541.46 1467.57,1541.46 1467.57,1565.09
TX1 on Top Layer "TOP-RX1 77" (solid, pour order 42): 1465.51,1659.14 1414.33,1659.14 1414.33,1611.11 1465.51,1611.11 1465.51,1659.14
GND on Top Layer "TOP-GND 27" (solid, remove dead copper, pour order 40): 1467.57,1541.46 1451.82,1541.46 1451.82,1515.17 1464.81,1515.17 1464.81,1491.38 1451.82,1491.38 1451.82,1449.34 1467.57,1449.34 1467.57,1475.63 1480.56,1475.63 1480.56,1530.92 1467.57,1530.92 1467.57,1541.46
TX1 on Top Layer "TOP-RX1 78" (solid, pour order 38): 1443.82,1580.83 1436.02,1580.83 1436.02,1541.46 1443.82,1541.46 1443.82,1580.83
TX1 on Top Layer "TOP-RX1 79" (solid, pour order 36): 1441.92,1611.11 1437.92,1611.11 1437.92,1580.83 1441.92,1580.83 1441.92,1611.11
TX1 on Top Layer "TOP-RX1 80" (solid, pour order 34): 1436.02,1492.61 1417.52,1492.61 1417.52,1484.81 1436.02,1484.81 1436.02,1492.61
TX1 on Top Layer "TOP-RX1 81" (solid, pour order 32): 1477.32,1767.72 1402.52,1767.72 1402.52,1719.69 1477.32,1719.69 1477.32,1767.72
GND on Top Layer "OUTLINE-No Net" (solid, remove dead copper, pour order 30): 1394.52,1906.58 1378.77,1906.58 1378.77,1580.83 1394.52,1580.83 1394.52,1906.58
TX1 on Top Layer "TOP-RX1 83" (solid, pour order 26): 1465.51,1876.31 1414.33,1876.31 1414.33,1828.28 1465.51,1828.28 1465.51,1876.31
GND on Top Layer "OUTLINE-No Net" (solid, remove dead copper, pour order 24): 1501.07,1906.58 1485.32,1906.58 1485.32,1580.83 1501.07,1580.83 1501.07,1906.58
GND on Top Layer "TOP-No Net 10" (solid, remove dead copper, pour order 22): 94 vertices, not listed, extent 1095.42,1449.32 1193.84,1922.31
GND on Top Layer "TOP-No Net 23" (solid, remove dead copper, pour order 20): 125 vertices, not listed, extent 891.67,1449.32 996.98,1922.31
GND on Top Layer "TOP-No Net 24" (solid, pour order 18): 35 vertices, not listed, extent 1292.28,1565.13 1299.17,1922.31
CB_PMIC_1V8 on Top Layer "CB_PMIC_1V8_L01_P006" (solid, remove dead copper, pour order 6): 1791,948 1797,942 1797,796 1773,772 1737,772 1719,790 1719,833 1742,856 1742,941 1749,948
MON_1V on Top Layer "MON_1V_L01_P004" (solid, remove dead copper, pour order 4): 22 vertices, not listed, extent 360,255 558.74,523
RX1 on Top Layer "TOP-No Net 43" (solid, remove dead copper, pour order 10): 38 vertices, not listed, extent 910.37,1449.32 985.17,1876.29
RX2 on Top Layer "TOP-No Net 42" (solid, remove dead copper, pour order 12): 38 vertices, not listed, extent 1008.8,1449.32 1083.6,1876.29
RX3 on Top Layer "TOP-No Net 41" (solid, remove dead copper, pour order 14): 38 vertices, not listed, extent 1107.23,1449.32 1182.03,1876.29
RX4 on Top Layer "TOP-No Net 40" (solid, remove dead copper, pour order 16): 38 vertices, not listed, extent 1205.66,1449.32 1280.46,1876.29
TX1 on Top Layer "TOP-RX1 82" (solid, remove dead copper, pour order 28): 1443.82,1488.71 1436.02,1488.71 1436.02,1449.34 1443.82,1449.34 1443.82,1488.71
GND on Top Layer "OUTLINE-No Net" (solid, remove dead copper, pour order 66): 1590.62,1614.78 1590.62,1559.49 1609.13,1559.49 1609.13,1547.76 1624.88,1547.76 1624.88,1575.24 1606.37,1575.24 1606.37,1599.03 1624.88,1599.03 1624.88,1639.89 1609.13,1639.89 1609.13,1614.78 1590.62,1614.78
GND on Top Layer "TOP-GND 27" (solid, remove dead copper, pour order 90): 1664.42,1639.89 1648.67,1639.89 1648.67,1613.6 1661.66,1613.6 1661.66,1589.8 1648.67,1589.8 1648.67,1547.76 1664.42,1547.76 1664.42,1574.05 1677.41,1574.05 1677.41,1629.35 1664.42,1629.35 1664.42,1639.89
TX2 on Top Layer "TOP-RX1 82" (solid, remove dead copper, pour order 102): 1640.67,1587.13 1632.88,1587.13 1632.88,1547.76 1640.67,1547.76 1640.67,1587.13
TX3 on Top Layer "TOP-RX1 82" (solid, remove dead copper, pour order 112): 1837.52,1488.71 1829.73,1488.71 1829.73,1449.34 1837.52,1449.34 1837.52,1488.71
GND on Top Layer "TOP-No Net 1" (solid, remove dead copper, pour order 152): 2125,20 1965,20 1950,35 1950,180 2015,245 2015,760 1960,815 1959.99,1154.99 1985,1180 2138.62,1180 2140,1178.62 2140,20.18
GND on Top Layer "TOP-No Net 1" (solid, remove dead copper, pour order 154): 215,20 30,20.18 30,2144 226,2144 226,700.93 170,644.93 170,235 215,190
RADAR_VOUT_PA on Top Layer "TOP-No Net 1" (solid, remove dead copper, pour order 198): 17 vertices, not listed, extent 1271.59,1206 1484.59,1320
GND on Top Layer "TOP-No Net" (solid, remove dead copper, pour order 204): 848.74,2143.96 667.78,2144.31 667.7,1528.04 727.62,1468.11 846.06,1468.11 848.74,1470.79
GND on Top Layer "TOP-No Net" (solid, remove dead copper, pour order 158): 1940.79,2143.88 2139.97,2144.28 2140.06,1387 1940.78,1386.99
GND on Top Layer "GND_L01_P218" (solid, remove dead copper, pour order 218): 1400,356 1400,291 1377,268 1363,268 1363,185 1423,125 1565,125 1574,134 1574,187 1520,241 1492,241 1463,270 1463,353 1451,365 1409,365
GND on Top Layer "TOP-No Net 1" (solid, remove dead copper, pour order 194): 818.74,360 830.74,348 830.74,312 861.74,281 861.74,199 881.74,179 881.74,144 864.74,127 781.99,127 777.65,131.35 777.64,297.36 743,332 742.99,349.99 752.99,359.99
NetC39_2 on Top Layer "TOP-No Net 1" (solid, remove dead copper, pour order 182): 22 vertices, not listed, extent 553.74,232.99 769,535
NetC39_2 on Top Layer "RADAR_1V8_L01_P-001" (solid, remove dead copper, pour order 456): 508.35,554.21 630.79,554.21 643.74,541.26 643.74,503.31 635.43,495 560,495 545,510 513.35,510 508.35,515
GND on Top Layer "TOP-No Net 11" (solid, remove dead copper, pour order 2): 94 vertices, not listed, extent 996.99,1449.32 1095.41,1922.31
GND on Top Layer "GND_L01_P448" (solid, remove dead copper, pour order 448): 33 vertices, not listed, extent 31,974 2140,2144.05
GND on L3 "RADAR_1V8_L01_P-001" (solid, remove dead copper, pour order 462): 559.13,468.85 723.01,468.85 796.83,542.67 851.69,542.67 896.39,497.97 896.39,447.86 726.72,278.19 638.52,278.19 526.96,389.75 526.96,449.17 546.64,468.85
CB_PMIC_1V0 on L3 "CB_PMIC_1V0_L03_P2968" (solid, remove dead copper, pour order 320): 24 vertices, not listed, extent 239.99,20.17 1634,1828
CB_PMIC_1V2 on L3 "BOTTOM-No Net" (solid, remove dead copper, pour order 318): 745,170 790,125 800,115 960,115 1020,175 1520,175 1555,210 1555,275 1555,310 1524.01,341 1319.3,339.29 1172.42,479.92 956.34,479.92 745,265
VCC_3V3 on L3 "RADAR_1V8_L01_P-001" (solid, remove dead copper, pour order 460): 857.27,689.16 921.72,689.16 993.76,617.12 993.76,532.46 982.38,521.08 915.73,521.08 848.11,588.7 848.11,680
RADAR_1V2 on L3 "RADAR_1V2_L03_P2940" (solid, remove dead copper, pour order 322): 19 vertices, not listed, extent 627,749.99 1186.2,1482
GND on L3 "BOTTOM-No Net" (solid, remove dead copper, pour order 330): 30 vertices, not listed, extent 1184,369 1770,886
GND on L3 "GND_L03_P3050" (solid, remove dead copper, pour order 332): 1013.99,1104.01 1079,1039 1079,1016.44 1166.44,929 1315,929 1399,1013 1619.2,1013 1710,1103.8 1710,1422 1620,1512 1089,1512 1013.99,1436.99
GND on L3 "RADAR_1V8_L01_P-001" (solid, remove dead copper, pour order 334): 25 vertices, not listed, extent 30,19.86 2140,2144
VCC_3V3 on L3 "VCC_3V3_L03_P2986" (solid, remove dead copper, pour order 326): 740,610 753,597 753,546 708,501 536,501 476,561 476,718 522,718 630,610
CB_PMIC_1V8 on L3 "CB_PMIC_1V8_L03_P2952" (solid, remove dead copper, pour order 324): 21 vertices, not listed, extent 1646,90 1850,844
5V_IN on L4 "5V_IN_L04_P2920" (solid, remove dead copper, pour order 364): 1917.64,210 1935,192.64 1935,50 1905,20 310,20 241,89 241,339 543.85,339 730.01,152.83 1667.83,152.83 1725,210
GND on L4 "RADAR_1V8_L01_P-001" (solid, remove dead copper, pour order 374): 21 vertices, not listed, extent 1290,427 1873,1068
VCC_3V3 on L4 "VCC_3V3_L04_P2992" (solid, remove dead copper, pour order 356): 28 vertices, not listed, extent 223,654.99 899,1807
RADAR_1V8 on L4 "RADAR_1V8_L04_P3008" (solid, remove dead copper, pour order 368): 25 vertices, not listed, extent 826,782 1694,1208
GND on L4 "BOTTOM-No Net" (solid, remove dead copper, pour order 372): 37 vertices, not listed, extent 30,20 2140,2144
GND on L4 "GND_L04_P370" (solid, remove dead copper, pour order 370): 261,645 425,645 447,623 447,382 421,356 277,356 226,407 226,610 252,636
PMIC_1V0 on L4 "PMIC_1V0_L04_P2966" (solid, remove dead copper, pour order 362): 20 vertices, not listed, extent 431,843 670,1334
CB_PMIC_1V2 on L4 "CB_PMIC_1V2_L04_P2962" (solid, remove dead copper, pour order 366): 23 vertices, not listed, extent 330,165 799,1491
VCC_3V3 on L4 "VCC_3V3_L04_P2984" (solid, remove dead copper, pour order 358): 23 vertices, not listed, extent 1210,169 1992,457
VCC_3V3 on L4 "VCC_3V3_L04_P2972" (solid, remove dead copper, pour order 360): 1318,320 1340,297.99 1340,234 1284.3,178.3 870.7,178.3 570,479 570,737 662,829 826,829 1141,514 1141,407 1174,374 1264,374
GND on Bottom Layer "GND_L06_P444" (solid, remove dead copper, pour order 444): 907,1386 924,1386 934,1376 934,1360 958,1336 1059,1336 1062,1333 1062,1284 1062,1241 1002,1241 998,1245 998,1254 954,1298 896,1298 896,1375
RADAR_3V3 on Bottom Layer "RADAR_3V3_L06_P386" (solid, remove dead copper, pour order 386): 29 vertices, not listed, extent 840,674 1151,1040
RADAR_1P0_RF1 on Bottom Layer "TOP-No Net 1" (solid, remove dead copper, pour order 442): 858.74,1440 863.74,1445 1085.59,1445 1105.59,1425 1105.59,1396.85 1073.74,1365 964.29,1365 932.43,1396.85 896.89,1396.85 869.04,1369 846.74,1369 846.74,1428
RADAR_1P0_RF1 on Bottom Layer "TOP-No Net 1" (solid, remove dead copper, pour order 440): 24 vertices, not listed, extent 945.59,1139 1160.59,1445
RADAR_1P0_RF2 on Bottom Layer "TOP-No Net 1" (solid, remove dead copper, pour order 408): 888.74,1600 1268.74,1600 1343.74,1525 1343.74,1350 1278.74,1350 1148.74,1480 846.74,1480 846.74,1558
GND on Bottom Layer "GND_L06_P438" (solid, remove dead copper, pour order 438): 776.18,151.18 840.82,151.18 863,129 863,63 847,47 776,47 764.99,58 765,140
GND on Bottom Layer "TOP-No Net 1" (solid, remove dead copper, pour order 426): 215,20 30,20.18 30,2144 30.99,2145 240,2145 240,1149 205,1114 205,678.94 170,643.94 170,235 215,190
GND on Bottom Layer "TOP-No Net 1" (solid, remove dead copper, pour order 382): 1965,20 2139.83,20 2140,2144 1941,2144 1940,2145 1940,1365 2020,1285 2020,970.91 1961.01,911.92 1961.01,829.23 2015.39,774.85 2015.39,235.39 1950,170 1950,35
GND on Bottom Layer "TOP-No Net 1" (solid, remove dead copper, pour order 380): 31,1871 228,1871 300,1943 2134,1943 2140,1949 2140,2144 30,2144 30,1870
GND on Bottom Layer "GND_L06_P430" (solid, remove dead copper, pour order 430): 1044,887 1133.99,887 1187.99,833 1209,833 1213,829 1213,808 1189,784 1166.99,784 1154,797 1154,826 1117,863 1044,863
PMIC_1V0 on Bottom Layer "PMIC_1V0_L06_P428" (solid, remove dead copper, pour order 428): 540,1327 629,1327 629,1231 602,1204 536,1204 525,1215 525,1312
CB_PMIC_1V0 on Bottom Layer "CB_PMIC_1V0_L06_P424" (solid, remove dead copper, pour order 424): 447,1334 465,1316 465,1225 452,1212 361,1212 345,1228 345,1303 376,1334
CB_PMIC_1V0 on Bottom Layer "CB_PMIC_1V0_L06_P422" (solid, remove dead copper, pour order 422): 800,1290 748,1290 725,1313 725,1480 651,1554 651,1681 665,1695 750,1695 825,1620 825,1380 805,1360 805,1295
CB_PMIC_1V2 on Bottom Layer "BOTTOM-No Net" (solid, remove dead copper, pour order 420): 856.22,245.9 865,237.12 865,220 865,158.07 771.92,158.07 765,165 765,200 765,236.1 774.8,245.9
VCC_LD_SW_3V3 on Bottom Layer "TOP-No Net 1" (solid, remove dead copper, pour order 414): 738.74,790 708.74,760 708.74,690 713.74,685 788.74,685 803.74,700 868.74,700 873.74,705 873.74,785 868.74,790
RADAR_1V8 on Bottom Layer "BOTTOM-AR_1V8" (solid, remove dead copper, pour order 412): 1170.02,1195 1128.74,1195 1121.59,1202.14 1121.59,1294.13 1170.02,1294.13 1170.02,1208.73
NetC61_1 on Bottom Layer "TOP-No Net" (solid, remove dead copper, pour order 404): 1080.74,532 1119.74,532 1128.74,523 1128.74,468 1121.74,461 1091.74,461 1074.74,444 1074.74,424 1032.74,382 1019.74,382 1010.74,391 1010.74,417 1074.74,481 1074.74,526
VCC_3V3 on Bottom Layer "TOP-No Net 1" (solid, remove dead copper, pour order 402): 1934,339.99 1942,348 1992,348 1997,343 1997,262 1978,243 1960,243 1894,309 1777,309 1777,340
5V_IN on Bottom Layer "TOP-No Net 1" (solid, remove dead copper, pour order 400): 1778,300 1877,300 1899,278 1899,235 1920,214 1920,165 1902,147 1882,147 1862,167 1862,213 1811,264 1783,264 1778,269
CB_PMIC_1V0 on Bottom Layer "CB_PMIC_1V0_L06_P2768" (solid, remove dead copper, pour order 398): 1554,320 1642,320 1652,310 1652,206 1638,192 1571,192 1554,209
CB_PMIC_1V2 on Bottom Layer "CB_PMIC_1V2_L06_P2772" (solid, remove dead copper, pour order 396): 1641,359 1641,330 1639,328 1542,328 1535,321 1535,291 1542,284.01 1542,247 1528,233 1494,233 1480,247 1480,309 1530,359
PMIC_1V24 on Bottom Layer "PMIC_1V24_L06_P2778" (solid, remove dead copper, pour order 394): 925,235 975,235 980,230 980,35 965,20 890,20 877.82,32.18 877.82,122.82 895,140 915,140 925,150
RADAR_1V8 on Bottom Layer "BOTTOM-AR_1V8" (solid, remove dead copper, pour order 392): 1170.02,1195 1128.74,1195 1121.59,1202.14 1121.59,1294.13 1170.02,1294.13 1170.02,1208.73
RADAR_1P0_RF2 on Bottom Layer "TOP-No Net 1" (solid, remove dead copper, pour order 384): 1331.74,1462 1344.74,1449.01 1344.74,1203.74 1332,1191 1281,1191 1275,1197 1275,1450.26 1286.74,1462
GND on Bottom Layer "RADAR_1V8_L01_P-001" (solid, remove dead copper, pour order 378): 1510,1993 1620,1883 1620,1503 1570,1453 1498,1453 1474,1477 1388,1477 1369,1496 1369,1562 1312,1619 975,1619 927,1667 927,1938 927,1993
5V_IN on Bottom Layer "TOP-No Net 1" (solid, remove dead copper, pour order 446): 19 vertices, not listed, extent 251,840 586.74,1066
GND on Bottom Layer "GND_L06_P432" (solid, remove dead copper, pour order 432): 1174,354 1138,354 1128,364 1128,438 1160,470 1160,542 1165,547 1207,547 1210.62,543.38 1210.62,432.79 1181,403.17 1181,361
GND on Bottom Layer "RADAR_1V8_L01_P-001" (solid, remove dead copper, pour order 452): 1017.49,176.85 1049.77,176.86 1053.41,173.22 1053.41,150.63 1070.85,133.19 1070.85,109.53 1055.74,94.42 1036.83,94.42 1015.07,116.18 1015.07,145.57 1009.2,151.44 1009.2,168.56
VCC_3V3 on Bottom Layer "TOP-No Net 1" (solid, remove dead copper, pour order 416): 581.22,73.02 613.9,73.02 618.88,78 660.74,78 675.49,92.75 727,92.75 727,34.26 709.74,17 597.74,17 581.22,33.52
GND on Bottom Layer "RADAR_1V8_L01_P-001" (solid, remove dead copper, pour order 458): 506.98,109.33 518.55,97.76 518.55,78.78 524.6,72.73 565.8,72.73 568.18,70.35 568.18,48.52 563.61,43.95 487.4,43.95 478.86,52.49 478.86,99.09 489.1,109.33
VCC_3V3 on Bottom Layer "VCC_3V3_L06_P468" (solid, remove dead copper, pour order 468): 1102.18,452.15 1090.9,441.77 1090.9,397.49 1066.43,373.02 1066.43,350.31 1069.83,346.91 1102.27,346.91 1120.19,364.83 1120.19,447.33 1115.37,452.15
GND on Bottom Layer "GND_L06_P472" (solid, remove dead copper, pour order 472): 954.05,322.83 969.2,322.83 1018.04,371.67 1051.55,371.67 1052.43,370.79 1052.43,348.97 1042.55,339.09 1042.55,303.13 1037.98,298.56 953.53,298.56 947.19,304.9 947.19,315.97
GND on Bottom Layer "GND_L06_P474" (solid, remove dead copper, pour order 474): 1155,185 1190,185 1200,175 1200,140 1215,125 1215,100 1205,90 1177,90 1155,112
RADAR_VOUT_PA on Bottom Layer "TOP-No Net 1" (solid, remove dead copper, pour order 410): 1460.59,1455 1485.59,1430 1485.59,1215 1470.59,1200 1430.59,1200 1421.27,1209.32 1421.27,1344.32 1379.05,1386.54 1366.52,1386.54 1360.59,1392.47 1360.59,1445 1370.59,1455
VCC_3V3 on Bottom Layer "VCC_3V3_L06_P476" (solid, remove dead copper, pour order 476): 575.16,811.7 453.91,811.7 435.67,793.46 435.67,711.07 439.29,707.45 465.88,707.45 472.25,713.82 472.25,772.13 480.72,780.6 575.16,780.6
